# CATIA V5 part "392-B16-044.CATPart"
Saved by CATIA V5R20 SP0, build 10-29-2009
Part number: 392-B16-044
Definition: NONE
Nomenclature: 392-B16-044
Source: Unknown
Description: 392-B16-044
Bounding box of the stored display mesh (mm): x 0 to 44, y -7.679 to 7.679, z -7.6 to 7.409
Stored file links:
  C:\Users\Utente\Desktop\IO LAVORO\3D X SITO CF\X SITO\3D files 392B\392-B16-044.CATPart
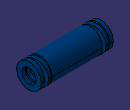
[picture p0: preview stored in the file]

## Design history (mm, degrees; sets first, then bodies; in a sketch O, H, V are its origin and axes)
Body1 "392-B16-044" (main body)
  Solid1: solid without history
